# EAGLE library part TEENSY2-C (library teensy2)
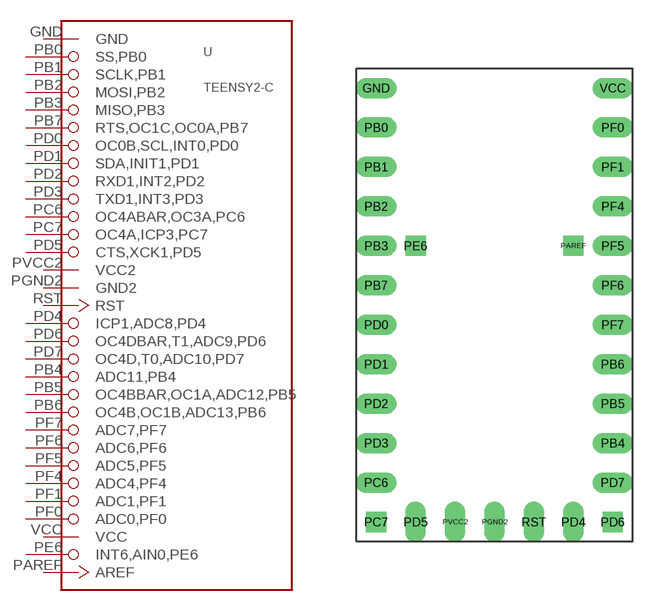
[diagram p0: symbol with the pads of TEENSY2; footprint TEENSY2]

Designator prefix -

## TEENSY2-CC-VERSION  [TEENSY2]
GND  GND  pwr
PAREF  AREF  in
PB0  SS,PB0
PB1  SCLK,PB1
PB2  MOSI,PB2
PB3  MISO,PB3
PB4  ADC11,PB4
PB5  OC4BBAR,OC1A,ADC12,PB5
PB6  OC4B,OC1B,ADC13,PB6
PB7  RTS,OC1C,OC0A,PB7
PC6  OC4ABAR,OC3A,PC6
PC7  OC4A,ICP3,PC7
PD0  OC0B,SCL,INT0,PD0
PD1  SDA,INIT1,PD1
PD2  RXD1,INT2,PD2
PD3  TXD1,INT3,PD3
PD4  ICP1,ADC8,PD4
PD5  CTS,XCK1,PD5
PD6  OC4DBAR,T1,ADC9,PD6
PD7  OC4D,T0,ADC10,PD7
PE6  INT6,AIN0,PE6
PF0  ADC0,PF0
PF1  ADC1,PF1
PF4  ADC4,PF4
PF5  ADC5,PF5
PF6  ADC6,PF6
PF7  ADC7,PF7
PGND2  GND2  pwr
PVCC2  VCC2  pwr
RST  RST  in
VCC  VCC  pwr

## Footprint TEENSY2 (pad centres in mm)
http://pjrc.com/teensy/index.html
drill 0.8 long: GND 12.7,21.59; PB0 12.7,19.05; PB1 12.7,16.51; PB2 12.7,13.97; PB3 12.7,11.43; PB4 27.94,-1.27; PB5 27.94,1.27; PB6 27.94,3.81; PB7 12.7,8.89; PC6 12.7,-3.81; PD0 12.7,6.35; PD1 12.7,3.81; PD2 12.7,1.27; PD3 12.7,-1.27; PD4 25.4,-6.35; PD5 15.24,-6.35; PD7 27.94,-3.81; PF0 27.94,19.05; PF1 27.94,16.51; PF4 27.94,13.97; PF5 27.94,11.43; PF6 27.94,8.89; PF7 27.94,6.35; PGND2 20.32,-6.35; PVCC2 17.78,-6.35; RST 22.86,-6.35; VCC 27.94,21.59
drill 0.8 square: PAREF 25.4,11.43; PC7 12.7,-6.35; PD6 27.94,-6.35; PE6 15.24,11.43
